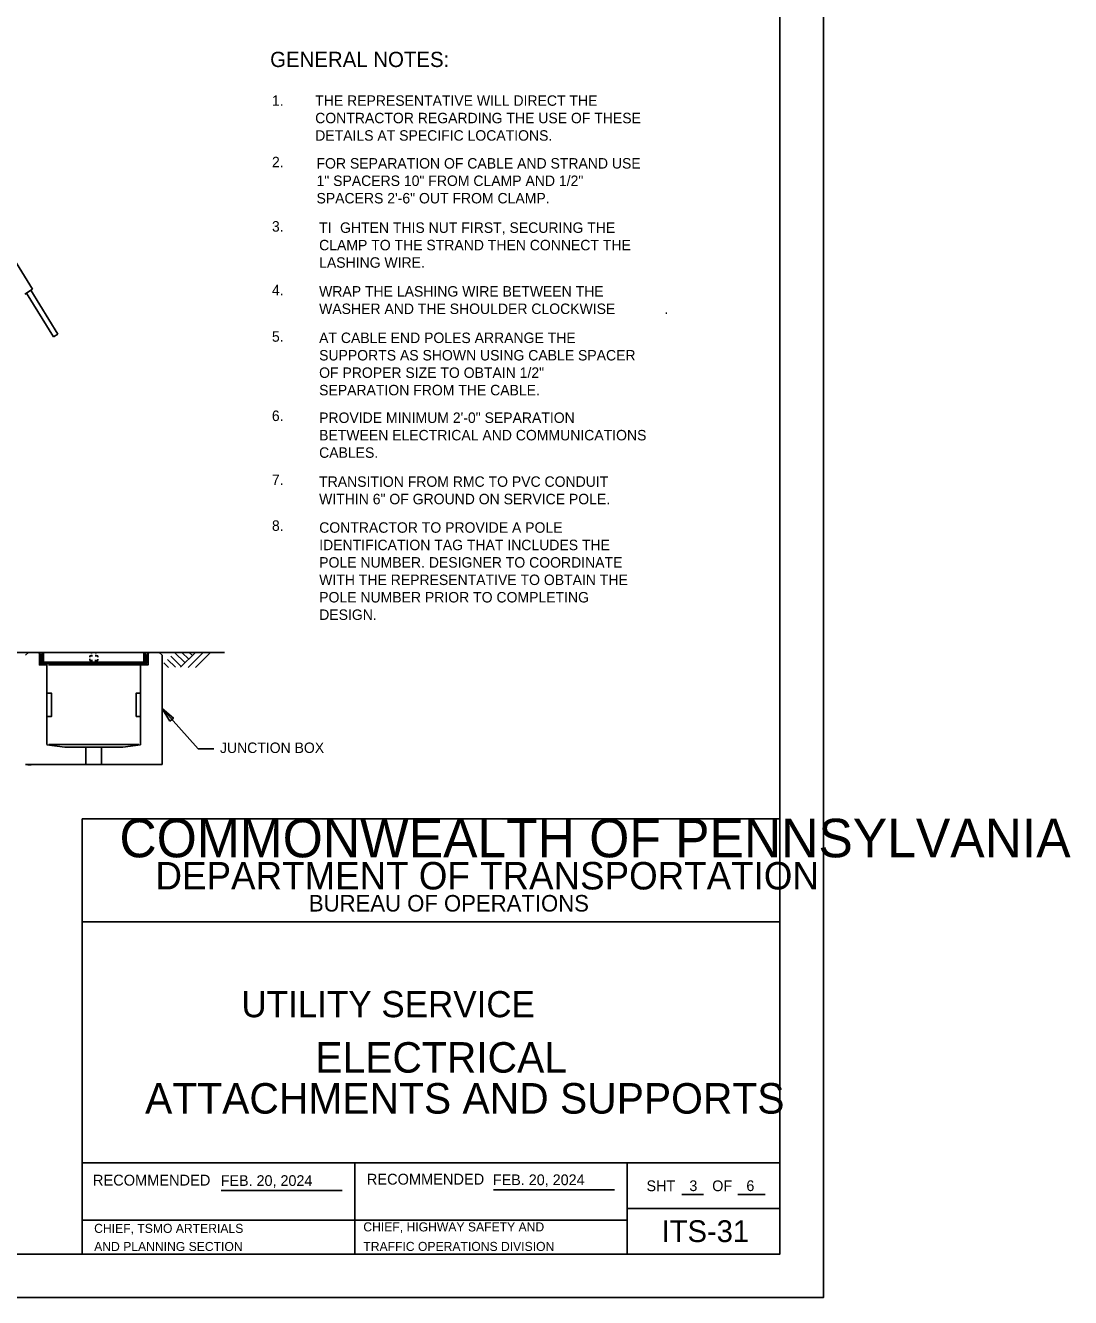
# Model space of a CAD drawing. Extents: x 1299104.8 to 1299141.6, y 239639.8 to 239661.8.
# Drawn here: x 1299129.65 to 1299141.64, y 239639.79 to 239654.39 of the extents above; entities that cross this region are included whole.
import ezdxf

# ---------------------------------------------------------------- set-up
doc = ezdxf.new("R2010")
doc.units = 0
for name, color, linetype in [('1', 7, 'Continuous'), ('2', 7, 'Continuous'), ('DIM TXT', 7, 'Continuous'), ('GS_noplot_1', 7, 'Continuous'), ('GS_plotshape_p', 7, 'Continuous'), ('Level 1', 7, 'Continuous'), ('PTEXT', 7, 'Continuous')]:
    doc.layers.add(name, color=color, linetype=linetype)

msp = doc.modelspace()

# ---------------------------------------------------------------- linework, layer by layer
at = {"layer": '1'}
for p, q in [((1299131.894, 239641.02), (1299133.284, 239641.02)), ((1299135.016, 239641.029), (1299136.405, 239641.029)), ((1299137.176, 239640.973), (1299137.427, 239640.973)), ((1299137.819, 239640.973), (1299138.133, 239640.973)), ((1299130.302, 239640.68), (1299133.427, 239640.68))]:
    msp.add_line(p, q, dxfattribs=at)
at = {"layer": 'DIM TXT'}
for p, q in [((1299129.139, 239652.323), (1299129.731, 239651.361)), ((1299129.642, 239651.306), (1299129.731, 239651.361)), ((1299129.661, 239651.318), (1299129.971, 239650.814)), ((1299129.712, 239651.35), (1299130.022, 239650.845)), ((1299129.971, 239650.814), (1299130.022, 239650.845)), ((1299125.154, 239647.194), (1299131.932, 239647.194)), ((1299129.65, 239647.161), (1299129.683, 239647.194)), ((1299129.683, 239647.194), (1299129.795, 239647.194)), ((1299129.795, 239647.194), (1299129.81, 239647.179)), ((1299129.81, 239647.179), (1299129.813, 239647.179)), ((1299129.81, 239647.179), (1299129.81, 239647.051)), ((1299129.843, 239647.194), (1299129.845, 239647.194)), ((1299129.843, 239647.194), (1299130.748, 239647.194)), ((1299129.858, 239647.194), (1299131.058, 239647.194)), ((1299129.915, 239647.082), (1299130.952, 239647.082)), ((1299129.928, 239647.069), (1299129.928, 239647.067)), ((1299129.928, 239647.067), (1299130.939, 239647.067)), ((1299129.957, 239647.067), (1299130.105, 239647.067)), ((1299130.169, 239647.067), (1299130.211, 239647.067)), ((1299130.183, 239647.067), (1299130.295, 239647.067)), ((1299130.388, 239647.139), (1299130.388, 239647.156)), ((1299130.388, 239647.156), (1299130.42, 239647.156)), ((1299130.388, 239647.102), (1299130.388, 239647.119)), ((1299130.388, 239647.102), (1299130.42, 239647.102)), ((1299130.408, 239647.194), (1299130.408, 239647.183)), ((1299130.408, 239647.166), (1299130.408, 239647.156)), ((1299130.408, 239647.102), (1299130.408, 239647.089)), ((1299130.408, 239647.067), (1299130.408, 239647.052)), ((1299130.446, 239647.102), (1299130.479, 239647.102)), ((1299130.448, 239647.156), (1299130.479, 239647.156)), ((1299130.459, 239647.194), (1299130.459, 239647.182)), ((1299130.459, 239647.166), (1299130.459, 239647.156)), ((1299130.459, 239647.102), (1299130.459, 239647.089)), ((1299130.459, 239647.067), (1299130.459, 239647.052)), ((1299130.479, 239647.141), (1299130.479, 239647.156)), ((1299130.479, 239647.102), (1299130.479, 239647.118)), ((1299130.748, 239647.194), (1299131.024, 239647.194)), ((1299130.939, 239647.069), (1299130.939, 239647.067)), ((1299131.024, 239647.194), (1299131.022, 239647.194)), ((1299131.022, 239647.194), (1299131.022, 239647.194)), ((1299131.056, 239647.179), (1299131.054, 239647.179)), ((1299131.056, 239647.179), (1299131.056, 239647.051)), ((1299131.183, 239647.194), (1299131.071, 239647.194)), ((1299131.216, 239647.161), (1299131.183, 239647.194)), ((1299131.217, 239647.161), (1299131.217, 239646.417)), ((1299131.217, 239647.161), (1299131.217, 239646.417)), ((1299131.237, 239647.073), (1299131.289, 239647.021)), ((1299131.279, 239647.114), (1299131.37, 239647.023)), ((1299131.317, 239647.151), (1299131.436, 239647.031)), ((1299131.361, 239647.194), (1299131.481, 239647.074)), ((1299131.428, 239647.023), (1299131.601, 239647.194)), ((1299131.444, 239647.194), (1299131.522, 239647.116)), ((1299131.517, 239647.022), (1299131.69, 239647.194)), ((1299131.528, 239647.194), (1299131.564, 239647.158)), ((1299131.6, 239647.022), (1299131.774, 239647.194)), ((1299129.81, 239647.051), (1299129.895, 239647.051)), ((1299129.895, 239647.054), (1299129.895, 239647.051)), ((1299129.895, 239647.051), (1299129.895, 239646.941)), ((1299129.895, 239646.941), (1299129.895, 239646.138)), ((1299129.915, 239647.051), (1299130.015, 239647.051)), ((1299130.015, 239647.051), (1299130.827, 239647.051)), ((1299130.827, 239647.051), (1299130.961, 239647.051)), ((1299130.971, 239647.054), (1299130.971, 239647.051)), ((1299131.056, 239647.051), (1299130.971, 239647.051)), ((1299130.971, 239647.051), (1299130.971, 239646.642)), ((1299130.971, 239646.642), (1299130.971, 239646.133)), ((1299131.216, 239646.637), (1299131.216, 239646.225)), ((1299131.63, 239646.086), (1299131.216, 239646.549)), ((1299129.895, 239646.269), (1299129.895, 239646.269)), ((1299130.971, 239646.278), (1299130.971, 239646.278)), ((1299130.971, 239646.269), (1299130.971, 239646.269)), ((1299131.216, 239646.247), (1299131.216, 239645.907)), ((1299131.217, 239646.225), (1299131.218, 239646.224)), ((1299129.895, 239646.133), (1299130.101, 239646.108)), ((1299129.917, 239646.138), (1299130.951, 239646.138)), ((1299130.101, 239646.108), (1299130.766, 239646.108)), ((1299130.344, 239646.108), (1299130.344, 239645.907)), ((1299130.522, 239646.108), (1299130.522, 239645.907)), ((1299130.971, 239646.133), (1299130.766, 239646.108)), ((1299131.809, 239646.086), (1299131.63, 239646.086)), ((1299131.216, 239645.907), (1299129.65, 239645.907)), ((1299129.68, 239645.907), (1299130.105, 239645.907))]:
    msp.add_line(p, q, dxfattribs=at)
for points in [[(1299129.895, 239647.051), (1299129.81, 239647.051), (1299129.81, 239647.179)], [(1299129.825, 239647.166), (1299129.825, 239647.067), (1299129.883, 239647.067)], [(1299129.928, 239647.067), (1299129.843, 239647.067), (1299129.843, 239647.194)], [(1299129.858, 239647.182), (1299129.858, 239647.082), (1299129.915, 239647.082)], [(1299130.939, 239647.067), (1299131.024, 239647.067), (1299131.024, 239647.194)], [(1299131.009, 239647.182), (1299131.009, 239647.082), (1299130.952, 239647.082)], [(1299130.971, 239647.051), (1299131.056, 239647.051), (1299131.056, 239647.179)], [(1299131.041, 239647.166), (1299131.041, 239647.067), (1299130.984, 239647.067)], [(1299131.138, 239647.194), (1299131.071, 239647.194), (1299131.056, 239647.179)], [(1299129.678, 239645.905), (1299129.679, 239645.905), (1299129.701, 239645.903), (1299129.713, 239645.904), (1299129.714, 239645.905)]]:
    msp.add_lwpolyline(points, dxfattribs=at)
for points in [[(1299129.895, 239646.457), (1299129.895, 239646.728), (1299129.947, 239646.728), (1299129.947, 239646.457)], [(1299130.92, 239646.457), (1299130.92, 239646.728), (1299130.971, 239646.728), (1299130.971, 239646.457)], [(1299131.306, 239646.405), (1299131.347, 239646.441), (1299131.216, 239646.549)]]:
    msp.add_lwpolyline(points, close=True, dxfattribs=at)
for centre, start, end in [((1299129.813, 239647.166), 0, 90), ((1299129.845, 239647.182), 0, 90), ((1299129.883, 239647.054), 0, 90), ((1299129.915, 239647.069), 0, 90), ((1299130.952, 239647.069), 90, 180), ((1299130.984, 239647.054), 90, 180), ((1299131.022, 239647.182), 90, 180), ((1299131.054, 239647.166), 90, 180)]:
    msp.add_arc(centre, 0.0128, start, end, dxfattribs=at)
at = {"layer": 'GS_noplot_1'}
msp.add_lwpolyline([(1299130.302, 239641.339), (1299136.552, 239641.339), (1299136.552, 239640.291), (1299130.302, 239640.291)], close=True, dxfattribs=at)
at = {"layer": 'GS_plotshape_p'}
msp.add_lwpolyline([(1299104.802, 239661.791), (1299138.802, 239661.791), (1299138.802, 239639.791), (1299104.802, 239639.791)], close=True, dxfattribs=at)
at = {"layer": 'Level 1'}
for p, q in [((1299130.302, 239641.339), (1299138.302, 239641.339)), ((1299133.427, 239641.339), (1299133.427, 239640.291)), ((1299136.552, 239640.815), (1299138.302, 239640.815)), ((1299133.427, 239640.68), (1299136.552, 239640.68))]:
    msp.add_line(p, q, dxfattribs=at)
for points in [[(1299138.302, 239640.291), (1299106.302, 239640.291), (1299106.302, 239661.291), (1299138.302, 239661.291)], [(1299138.302, 239645.284), (1299130.302, 239645.284), (1299130.302, 239644.104), (1299138.302, 239644.104)], [(1299138.302, 239645.284), (1299130.302, 239645.284), (1299130.302, 239640.291), (1299138.302, 239640.291)]]:
    msp.add_lwpolyline(points, close=True, dxfattribs=at)

# ---------------------------------------------------------------- texts
at = {"layer": '1'}
for s, height, p in [('COMMONWEALTH OF PENNSYLVANIA', 0.44223, (1299130.728, 239644.843)), ('DEPARTMENT OF TRANSPORTATION', 0.31514, (1299131.141, 239644.474)), ('BUREAU OF OPERATIONS', 0.18955, (1299132.901, 239644.221)), ('RECOMMENDED', 0.125, (1299130.424, 239641.076)), ('FEB. 20, 2024', 0.12303, (1299131.889, 239641.072)), ('RECOMMENDED', 0.125, (1299133.565, 239641.087)), ('FEB. 20, 2024', 0.12303, (1299135.011, 239641.081)), ('CHIEF, TSMO ARTERIALS ', 0.10417, (1299130.438, 239640.533)), ('CHIEF, HIGHWAY SAFETY AND ', 0.10417, (1299133.525, 239640.55)), ('AND PLANNING SECTION', 0.10417, (1299130.438, 239640.325)), ('TRAFFIC OPERATIONS DIVISION', 0.10417, (1299133.525, 239640.326))]:
    msp.add_text(s, height=height, dxfattribs=at).set_placement(p)
at = {"layer": '2'}
for s, p in [('SHT', (1299136.773, 239641.012)), ('3', (1299137.264, 239641.013)), ('OF', (1299137.526, 239641.012)), ('6', (1299137.918, 239641.013))]:
    msp.add_text(s, height=0.123, dxfattribs=at).set_placement(p)
at = {"layer": 'DIM TXT'}
for s, height, p in [('GENERAL NOTES:', 0.175, (1299132.456, 239653.911)), ('1.', 0.12, (1299132.477, 239653.466)), ('THE REPRESENTATIVE WILL DIRECT THE ', 0.12, (1299132.973, 239653.466)), ('CONTRACTOR REGARDING THE USE OF THESE ', 0.12, (1299132.973, 239653.266)), ('DETAILS AT SPECIFIC LOCATIONS.', 0.12, (1299132.973, 239653.066)), ('2.', 0.12, (1299132.477, 239652.761)), ('FOR SEPARATION OF CABLE AND STRAND USE ', 0.12, (1299132.988, 239652.746)), ('1" SPACERS 10" FROM CLAMP AND 1/2" ', 0.12, (1299132.988, 239652.546)), ('SPACERS 2\'-6" OUT FROM CLAMP.', 0.12, (1299132.988, 239652.346)), ('3.', 0.12, (1299132.477, 239652.023)), ('TI', 0.12, (1299133.018, 239652.008)), ('GHTEN THIS NUT FIRST, SECURING THE ', 0.12, (1299133.258, 239652.008)), ('CLAMP TO THE STRAND THEN CONNECT THE ', 0.12, (1299133.018, 239651.808)), ('LASHING WIRE.', 0.12, (1299133.018, 239651.608)), ('4.', 0.12, (1299132.477, 239651.292)), ('WRAP THE LASHING WIRE BETWEEN THE ', 0.12, (1299133.018, 239651.277)), ('WASHER AND THE SHOULDER CLOCKWISE', 0.12, (1299133.018, 239651.077)), ('.', 0.12, (1299136.978, 239651.077)), ('5.', 0.12, (1299132.477, 239650.759)), ('AT CABLE END POLES ARRANGE THE ', 0.12, (1299133.018, 239650.744)), ('SUPPORTS AS SHOWN USING CABLE SPACER ', 0.12, (1299133.018, 239650.544)), ('OF PROPER SIZE TO OBTAIN 1/2" ', 0.12, (1299133.018, 239650.344)), ('SEPARATION FROM THE CABLE.', 0.12, (1299133.018, 239650.144)), ('6.', 0.12, (1299132.476, 239649.849)), ('PROVIDE MINIMUM 2\'-0" SEPARATION ', 0.12, (1299133.018, 239649.827)), ('BETWEEN ELECTRICAL AND COMMUNICATIONS ', 0.12, (1299133.018, 239649.627)), ('CABLES.', 0.12, (1299133.018, 239649.427)), ('7.', 0.12, (1299132.476, 239649.114)), ('TRANSITION FROM RMC TO PVC CONDUIT ', 0.12, (1299133.018, 239649.094)), ('WITHIN 6" OF GROUND ON SERVICE POLE.', 0.12, (1299133.018, 239648.894)), ('8.', 0.12, (1299132.477, 239648.589)), ('CONTRACTOR TO PROVIDE A POLE ', 0.12, (1299133.019, 239648.567)), ('IDENTIFICATION TAG THAT INCLUDES THE ', 0.12, (1299133.019, 239648.367)), ('POLE NUMBER. DESIGNER TO COORDINATE ', 0.12, (1299133.019, 239648.167)), ('WITH THE REPRESENTATIVE TO OBTAIN THE ', 0.12, (1299133.019, 239647.967)), ('POLE NUMBER PRIOR TO COMPLETING ', 0.12, (1299133.019, 239647.767)), ('DESIGN.', 0.12, (1299133.019, 239647.567)), ('JUNCTION BOX', 0.12, (1299131.881, 239646.04)), ('ITS-31', 0.25, (1299136.946, 239640.428))]:
    msp.add_text(s, height=height, dxfattribs=at).set_placement(p)
at = {"layer": 'PTEXT'}
for s, height, p in [('UTILITY SERVICE', 0.3, (1299132.127, 239643.008)), ('ELECTRICAL', 0.35, (1299132.974, 239642.372)), ('ATTACHMENTS AND SUPPORTS', 0.35, (1299131.022, 239641.902))]:
    msp.add_text(s, height=height, dxfattribs=at).set_placement(p)

doc.saveas('drawing.dxf')
